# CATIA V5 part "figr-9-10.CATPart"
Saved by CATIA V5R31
Part number: Part1
Bounding box of the stored display mesh (mm): x -15.705 to 98.193, y 0 to 272.268, z -20.723 to 20.723
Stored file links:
  D:\PROJECTS\Project 2021\US EDITION\CATIA V5 6R 2021\Resources\Part Files\c09_catia_v5_6r2021_prt\c09_catia_v5_6r2021_prt\figr-9-10.CATPart
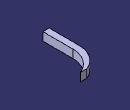
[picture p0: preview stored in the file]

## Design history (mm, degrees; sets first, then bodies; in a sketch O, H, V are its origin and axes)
Body1 (main body)
  Sketch1 on xy-plane, origin (0, 0, 0), H (1, 0, 0), V (0, 1, 0)
    line L1 (0, 0) -> (0, 150)
    arc A1 centre (131.8599, 150) radius 131.8599 from (0, 150) to (82.4884, 272.2681) cw
    length L1 = 150
    tangency: A1 L1
  Sketch2 on zx-plane, origin (0, 0, 0), H (-1, 0, 0), V (0, 0, 1)
    line L1 (15.7048, 20.7231) -> (15.7048, -20.7231)
    line L2 (15.7048, -20.7231) -> (-15.7048, -20.7231)
    line L3 (-15.7048, -20.7231) -> (-15.7048, 20.7231)
    line L4 (-15.7048, 20.7231) -> (15.7048, 20.7231)
    vertical: L1 V, L3 V
    horizontal: L2 H, L4 H
    equidistance: L1 L3 O, L2 L4 O
  Rib1: profile Sketch2, centre curve Sketch1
